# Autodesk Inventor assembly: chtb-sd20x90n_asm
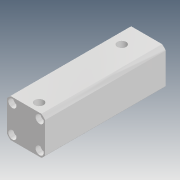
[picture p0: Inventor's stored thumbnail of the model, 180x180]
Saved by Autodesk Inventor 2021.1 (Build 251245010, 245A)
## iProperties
Company: Microsoft
Created: 2018-04
Part Number: chtb-sd20x90n_asm
Description: STEP AP214
Document SubType Name: Assembly
Designer: user
Title: chtb-sd20x90n_asm.STEP
Author: Windows
Revision Number: ÈÎºÎ
Sending System: SolidWorks 2015
Preprocessor: SwSTEP 2.0
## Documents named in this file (4)
- D:\Vault_2016\Projekty\Clamptek\Hydraulic\CHTB\CHTB-20\Inventor\CHTB-SD20x90N\chtb-sd20x90n_asm.iam
- D:\Vault_2016\Projekty\Clamptek\Hydraulic\CHTB\CHTB-20\Inventor\CHTB-SD20x90N\CHTB-SD20X90NBT.ipt
- D:\Vault_2016\Projekty\Clamptek\Hydraulic\CHTB\CHTB-20\Inventor\CHTB-SD20x90N\CHTB-SD20X90NHSG.ipt
- D:\Vault_2016\Projekty\Clamptek\Hydraulic\CHTB\CHTB-20\Inventor\CHTB-SD20x90N\QG.ipt
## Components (3 placed, 3 different names)
1. CHTB-SD20X90NBT_1
2. CHTB-SD20X90NHSG_2
3. QG_3
